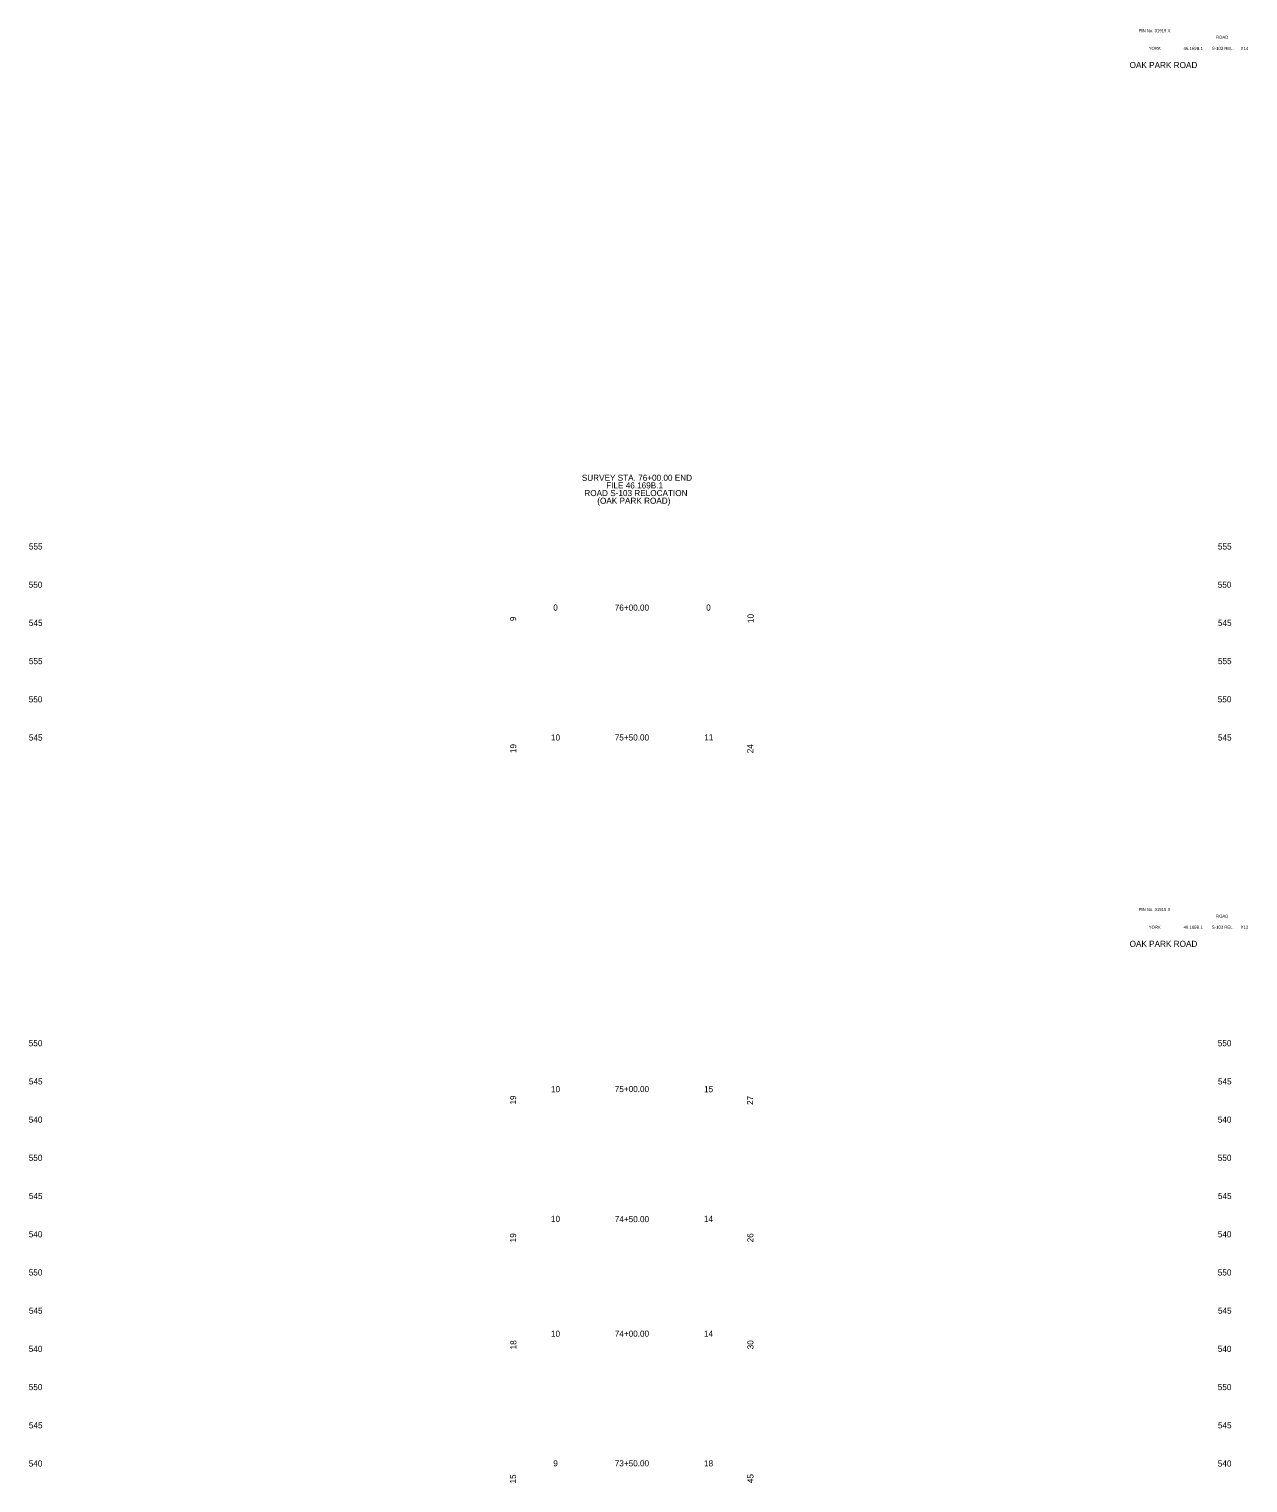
# Model space of a CAD drawing. Extents: x 1001 to 1161, y 1003 to 2598.
# Drawn here: x 1001.2 to 1160.6, y 2408 to 2598.2 of the extents above; entities that cross this region are included whole.
import ezdxf

# ---------------------------------------------------------------- set-up
doc = ezdxf.new("R2010")
doc.units = 0
for name, color, linetype in [('RD_SHT_TX', 7, 'Continuous'), ('RD_TX_EndArea', 7, 'Continuous'), ('RD_TX_Volume', 7, 'Continuous'), ('RD_XS_TX_Elev_EX', 7, 'Continuous'), ('RD_XS_TX_Notes', 7, 'Continuous'), ('RD_XS_TX_Station', 7, 'Continuous')]:
    doc.layers.add(name, color=color, linetype=linetype)

msp = doc.modelspace()

# ---------------------------------------------------------------- texts
at = {"layer": 'RD_SHT_TX'}
for s, height, p in [('PIN No. 31919 X', 0.4, (1146.28, 2597.8)), ('ROAD', 0.4, (1156.41, 2596.93)), ('YORK', 0.4, (1147.6, 2595.48)), ('46.169B.1', 0.4, (1152.16, 2595.48)), ('S-103 REL.', 0.4, (1155.86, 2595.48)), ('X14', 0.4, (1159.63, 2595.48)), ('OAK PARK ROAD', 0.8, (1145.1, 2593.1)), ('PIN No. 31919 X', 0.4, (1146.28, 2482.8)), ('YORK', 0.4, (1147.6, 2480.48)), ('46.169B.1', 0.4, (1152.16, 2480.48)), ('S-103 REL.', 0.4, (1155.86, 2480.48)), ('ROAD', 0.4, (1156.41, 2481.93)), ('X13', 0.4, (1159.64, 2480.48)), ('OAK PARK ROAD', 0.8, (1145.1, 2478.1))]:
    msp.add_text(s, height=height, dxfattribs=at).set_placement(p)
at = {"layer": 'RD_TX_EndArea'}
for s, p in [('0', (1069.73, 2522.11)), ('0', (1089.73, 2522.11)), ('10', (1069.43, 2505.11)), ('11', (1089.48, 2505.13)), ('10', (1069.43, 2459.09)), ('15', (1089.45, 2459.09)), ('10', (1069.43, 2442.11)), ('14', (1089.43, 2442.11)), ('10', (1069.43, 2427.08)), ('14', (1089.43, 2427.08)), ('9', (1069.73, 2410.12)), ('18', (1089.44, 2410.12))]:
    msp.add_text(s, height=0.8, dxfattribs=at).set_placement(p)
at = {"layer": 'RD_TX_Volume'}
for s, p in [('9', (1064.87, 2520.73)), ('10', (1095.93, 2520.48)), ('19', (1064.89, 2503.46)), ('24', (1095.88, 2503.44)), ('19', (1064.87, 2457.47)), ('27', (1095.86, 2457.42)), ('19', (1064.87, 2439.44)), ('26', (1095.9, 2439.44)), ('18', (1064.91, 2425.43)), ('30', (1095.91, 2425.44)), ('15', (1064.87, 2407.88)), ('45', (1095.91, 2407.93))]:
    msp.add_text(s, height=0.8, rotation=90, dxfattribs=at).set_placement(p)
at = {"layer": 'RD_XS_TX_Elev_EX'}
for s, p in [('555', (1001.15, 2530.1)), ('555', (1156.65, 2530.1)), ('550', (1001.13, 2525.1)), ('550', (1156.63, 2525.1)), ('545', (1001.15, 2520.1)), ('545', (1156.65, 2520.1)), ('555', (1001.15, 2515.1)), ('555', (1156.65, 2515.1)), ('550', (1001.13, 2510.1)), ('550', (1156.63, 2510.1)), ('545', (1001.15, 2505.1)), ('545', (1156.65, 2505.1)), ('550', (1001.13, 2465.1)), ('550', (1156.63, 2465.1)), ('545', (1001.15, 2460.1)), ('545', (1156.65, 2460.1)), ('540', (1001.13, 2455.1)), ('540', (1156.63, 2455.1)), ('550', (1001.13, 2450.1)), ('550', (1156.63, 2450.1)), ('545', (1001.15, 2445.1)), ('545', (1156.65, 2445.1)), ('540', (1001.13, 2440.1)), ('540', (1156.63, 2440.1)), ('550', (1001.13, 2435.1)), ('550', (1156.63, 2435.1)), ('545', (1001.15, 2430.1)), ('545', (1156.65, 2430.1)), ('540', (1001.13, 2425.1)), ('540', (1156.63, 2425.1)), ('550', (1001.13, 2420.1)), ('550', (1156.63, 2420.1)), ('545', (1001.15, 2415.1)), ('545', (1156.65, 2415.1)), ('540', (1001.13, 2410.1)), ('540', (1156.63, 2410.1))]:
    msp.add_text(s, height=0.8, dxfattribs=at).set_placement(p)
at = {"layer": 'RD_XS_TX_Notes'}
for s, p in [('SURVEY STA. 76+00.00 END', (1073.46, 2539.09)), ('FILE 46.169B.1', (1076.65, 2538.09)), ('ROAD S-103 RELOCATION', (1073.79, 2537.09)), ('(OAK PARK ROAD)', (1075.48, 2536.09))]:
    msp.add_text(s, height=0.8, dxfattribs=at).set_placement(p)
at = {"layer": 'RD_XS_TX_Station'}
for s, p in [('76+00.00', (1077.77, 2522.1)), ('75+50.00', (1077.77, 2505.11)), ('75+00.00', (1077.77, 2459.1)), ('74+50.00', (1077.77, 2442.08)), ('74+00.00', (1077.77, 2427.09)), ('73+50.00', (1077.77, 2410.12))]:
    msp.add_text(s, height=0.8, dxfattribs=at).set_placement(p)

doc.saveas('drawing.dxf')
